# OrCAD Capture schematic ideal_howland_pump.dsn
size A
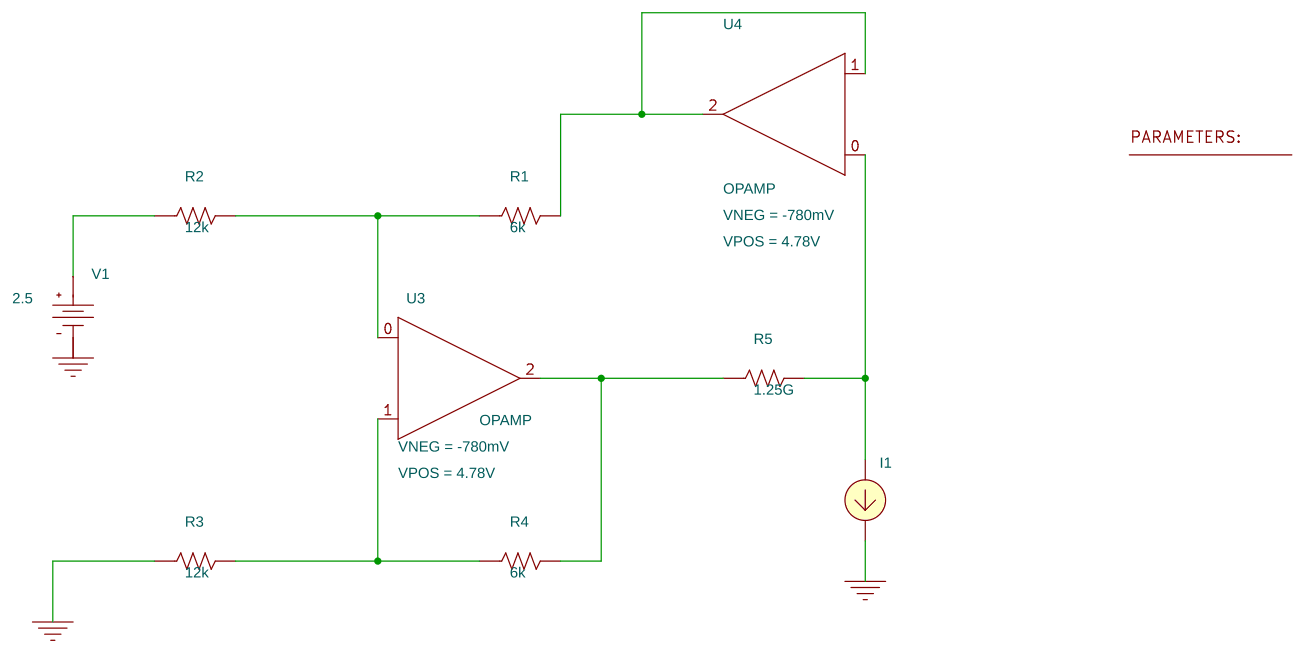
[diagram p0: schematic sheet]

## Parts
1  PARAM
I1  IDC
R1  6k  [AXRC05]
R2  12k  [AXRC05]
R3  12k  [AXRC05]
R4  6k  [AXRC05]
R5  1.25G  [AXRC05]
U3  OPAMP
U4  OPAMP
V1  VDC

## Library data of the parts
1 = PARAM: RTOL: 0.0001
I1 = IDC
R1-R4 = R: TOLERANCE: {RTOL}
R5 = R
U3 U4 = OPAMP: VNEG: -780mV; VPOS: 4.78V
V1 = VDC: DC: 2.5

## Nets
0: I1.2(-) R3.1 V1.1(-)
N00968: R1.2 U4.1(-) U4.2(OUT)
N01016: I1.1(+) R5.2 U4.0(+)
N01052: R2.1 V1.0(+)
N01060: R1.1 R2.2 U3.0(+)
N01130: R4.2 R5.1 U3.2(OUT)
N01150: R3.2 R4.1 U3.1(-)
